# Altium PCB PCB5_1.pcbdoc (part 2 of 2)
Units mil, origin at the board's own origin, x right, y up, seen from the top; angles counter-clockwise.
Board outline 4312.83 x 4315.15 mil, 4 copper layers (Top Layer, Inner1, Inner2, Bottom Layer); 84 components, 70 nets, 244 pads, 79 vias.
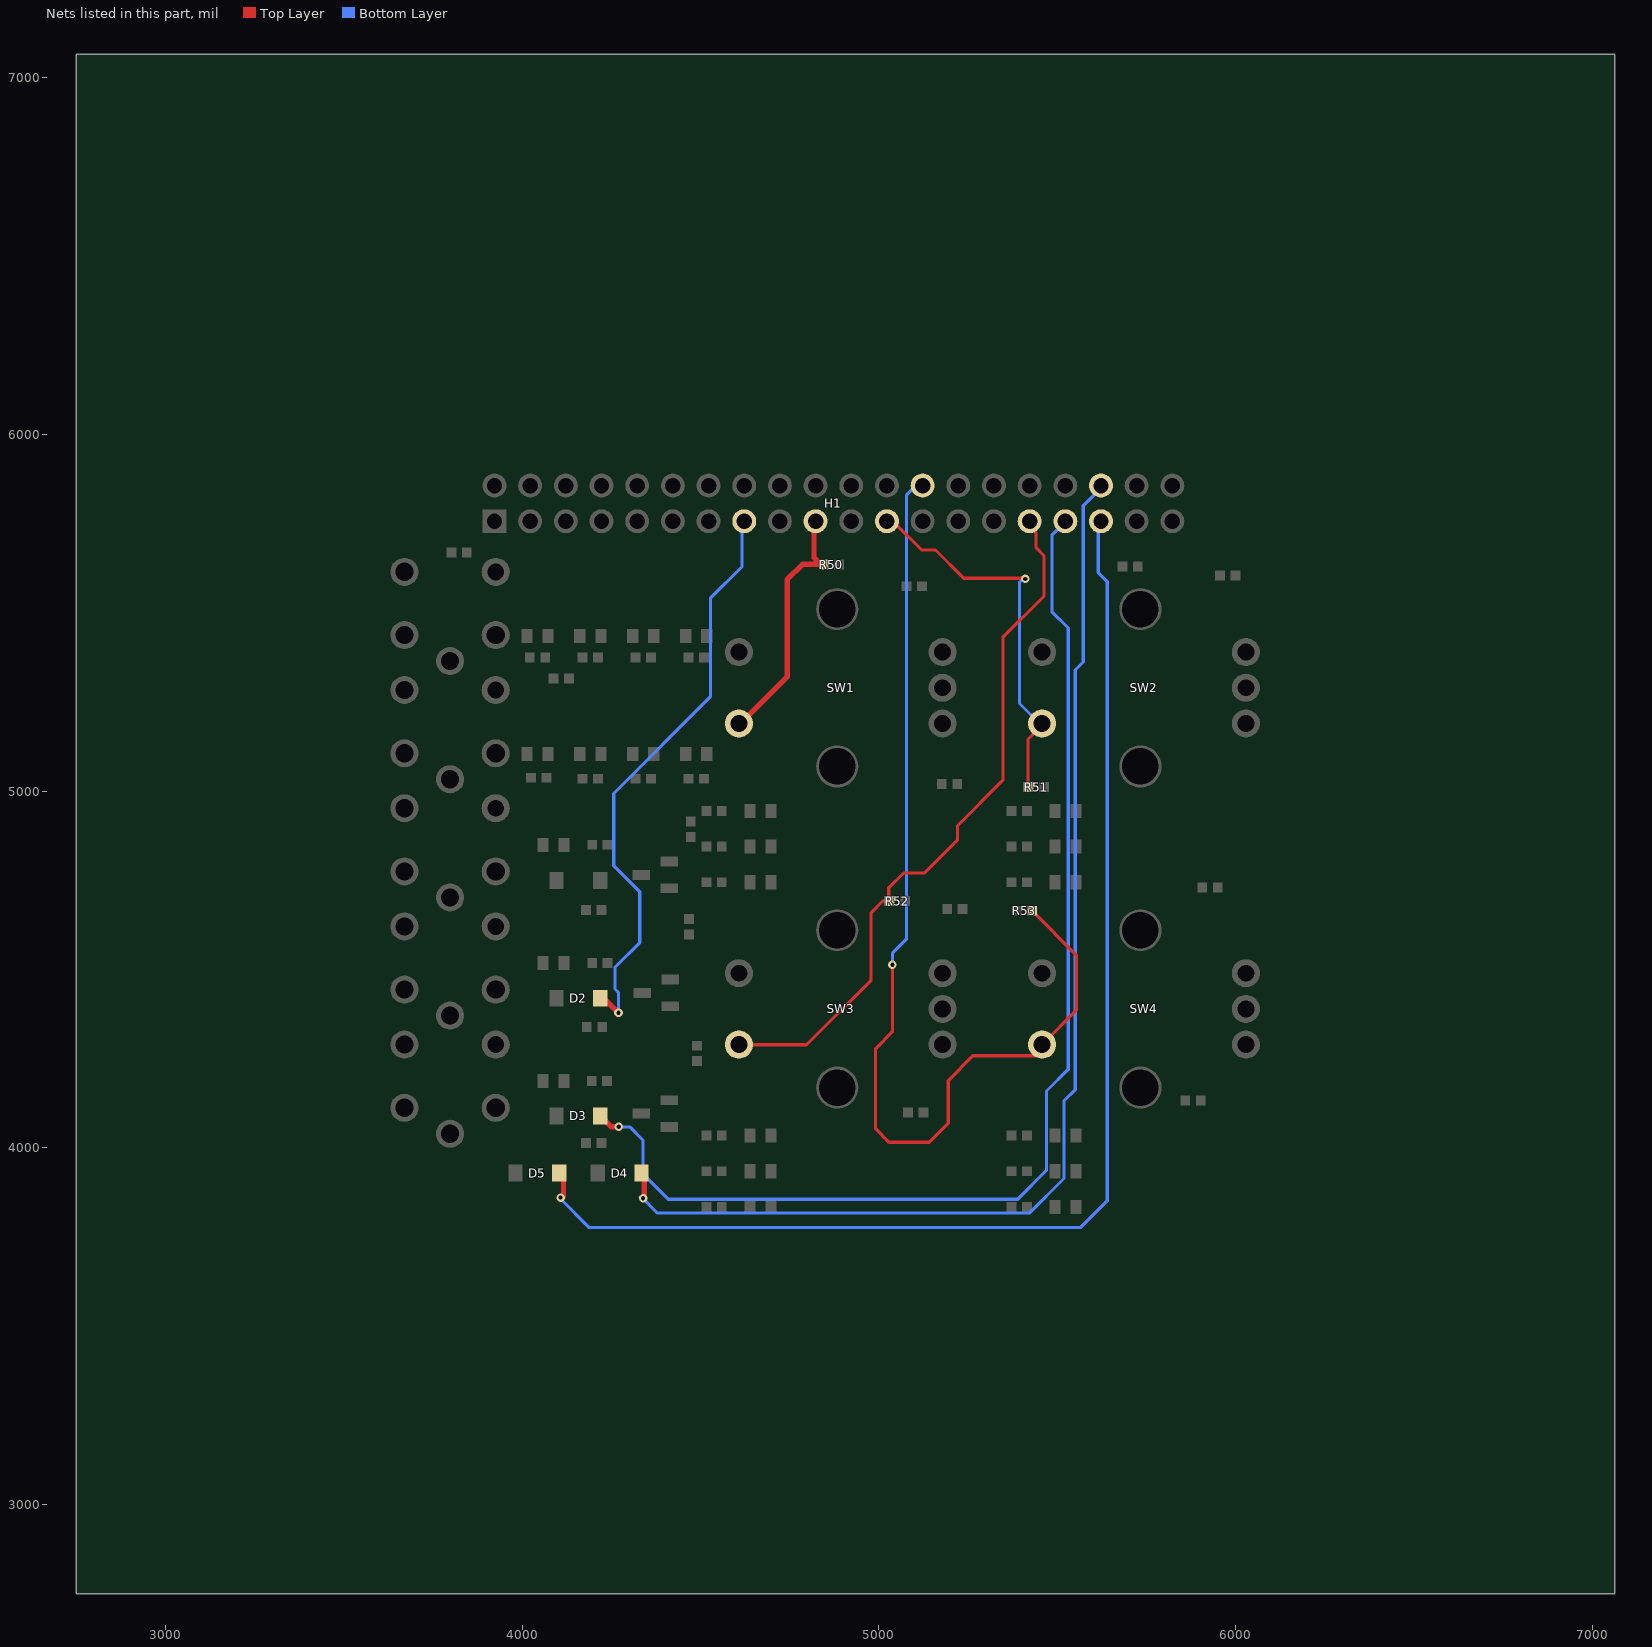
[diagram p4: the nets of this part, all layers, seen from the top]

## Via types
v1: diameter 24.02, hole 12.01, Top Layer to Bottom Layer, 69 vias
v2: diameter 30, hole 15, Top Layer to Bottom Layer, 7 vias
v3: diameter 24, hole 12, Top Layer to Bottom Layer, 2 vias
v4: diameter 32, hole 18, Top Layer to Bottom Layer, 1 vias

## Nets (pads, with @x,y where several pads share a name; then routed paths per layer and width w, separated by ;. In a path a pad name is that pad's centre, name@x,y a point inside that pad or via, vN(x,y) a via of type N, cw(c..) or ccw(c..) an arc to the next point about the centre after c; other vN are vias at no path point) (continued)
SW_BASS: H1.31 R52.1 SW3.1 | length 1952.4
  Top Layer w9: SW3.1@4617.91,4288.85 4796.83,4288.85 4978.01,4470.03 4978.01,4659.22 5010.5,4691.71 R52.1@5027.41,4691.71 ; R52.1@5028.61,4691.71 R52.1@5027.41,4691.71 ; H1.31@5434.53,5729.4 5439.76,5724.18 5439.76,5682.88 5462.65,5659.98 5462.65,5546.2 5347.42,5430.98 5347.42,5030.3 5220.5,4903.38 5220.5,4862.99 5127.44,4769.94 5068.67,4769.94 5027.41,4728.68 R52.1@5027.41,4691.71
SW_CHG_ROOM: D5.1 H1.35 | length 3568.9
  Top Layer w15: D5.1@4106.6,3924.24 4115.75,3915.09 v1@4115.75,3862.31
  Bottom Layer w9: v1@4107.8,3856.43 4187.76,3776.47 5564.57,3776.47 5639.93,3851.83 5639.93,5587.03 5614.66,5612.31 5614.66,5734.44 H1.35@5624.33,5744.11
  other v1: 4107.57,3860.48
SW_CHG_SPK: D4.1 H1.36 | length 3277.3
  Top Layer w15: D4.1@4334.61,3923.53 4342.35,3915.79 v1@4342.35,3863.01
  Bottom Layer w9: v1@4331.05,3861.57 4334.53,3861.57 4379.14,3816.97 5421.56,3816.97 5518.66,3914.06 5518.66,4131.87 5549.95,4163.16 5549.95,5339.23 5572.3,5361.59 5572.3,5799.43 5612.02,5839.15 H1.36@5612.02,5842.63
  other v1: 4338.86,3858.84
SW_EXTRA: H1.26 R53.1 SW4.1 | length 2989.2
  Top Layer w9: v1(5037.77,4513.1) 5037.77,4324.76 4990.51,4277.5 4990.51,4052.84 5027.87,4015.48 5141.08,4015.48 5193.91,4068.31 5193.91,4188.31 5263.35,4257.75 5438.83,4257.75 5461.09,4280.01 SW4.1@5461.09,4283.79 ; R53.1@5431.93,4661.05 5553.33,4539.66 5553.33,4385.55 SW4.1@5458.32,4290.55
  Bottom Layer w9: v1(5037.77,4513.1) 5037.77,4544.97 5076.79,4583.99 5076.79,5828.63 H1.26@5110.59,5862.43
SW_SINGLE_ROOM: D3.1 H1.33 | length 3292
  Top Layer w15: D3.1@4221.9,4086.45 4248.99,4059.35 v1(4270.51,4059.35)
  Bottom Layer w9: v1@4273.72,4057.96 4302.27,4057.96 4338.43,4021.8 4338.43,3926.75 4409.35,3855.83 5388.74,3855.83 5469.5,3936.59 5469.5,4159.29 5530.53,4220.33 5530.53,5456.98 5484.82,5502.69 5484.82,5717.23 H1.33@5512.18,5744.59
SW_SINGLE_SPK: D2.1 H1.15 | length 1656.8
  Top Layer w15: D2.1@4219.08,4422.82 4225.41,4422.82 v1(4269.92,4378.31)
  Bottom Layer w9: v1@4269.69,4379.42 4269.69,4435.61 4260.17,4445.13 4260.17,4506.27 4329.19,4575.29 4329.19,4717.84 4256.32,4790.71 4256.32,4993.03 4527.61,5264.31 4527.61,5540.6 4616.27,5629.27 H1.15@4616.27,5755.15
SW_TREB: H1.23 R51.1 SW2.1 | length 1071.6
  Top Layer w9: H1.23@5023.21,5744.01 5051.36,5744.01 5119.79,5675.58 5158.4,5675.58 5237.75,5596.23 v3@5410.96,5596.23 ; R51.1@5418,5012.71 5418,5145.71 SW2.1@5453.19,5180.89
  Bottom Layer w9: v3@5404.04,5595.33 5393.98,5585.27 5393.98,5245.38 SW2.1@5454.61,5184.75
  other v3: 5410.08,5594.57
SW_VOL: H1.19 R50.1 SW1.1 | length 689
  Top Layer w15: SW1.1@4608.98,5186.36 4742.57,5319.95 4742.57,5592.41 4785.6,5635.43 R50.1@4836.92,5635.43 ; H1.19@4818.05,5738.83 4818.05,5654.3 R50.1@4836.92,5635.43 ; R50.1@4839.94,5632.41 R50.1@4836.92,5635.43
pads on no net: SW1.6 SW1.7 SW2.6 SW2.7 SW3.6 SW3.7 SW4.6 SW4.7 SW5.4 SW6.4 SW7.4 SW8.4 SW9.4

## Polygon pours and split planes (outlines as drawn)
$2N557 on Bottom Layer (solid, pour order 16): 5129.22,4068.54 ccw(c5097.97,4068.18) 5066.71,4068.54 ccw(c5097.97,4068.9)
$2N1087 on Bottom Layer (solid, pour order 18): 4486.88,3980.93 ccw(c4435.15,3980.93) 4383.43,3980.93 ccw(c4435.15,3980.93)
$2N557 on Bottom Layer (solid, pour order 20): 4559.19,4097.4 ccw(c4508.6,4097.4) 4458.01,4097.4 ccw(c4508.6,4097.4)
GND on Bottom Layer (solid, remove dead copper, pour order 22): 6812.83,4906.18 ccw(c4906.65,4906.18) 3000.46,4906.18 ccw(c4906.65,4906.18)
$2N557 on Top Layer (solid, pour order 8): 4361.98,4799.29 ccw(c4313.08,4799.29) 4264.18,4799.29 ccw(c4313.08,4799.29)
$2N1087 on Top Layer (solid, pour order 10): 4366.38,4466.56 ccw(c4320.87,4466.56) 4275.36,4466.56 ccw(c4320.87,4466.56)
+3.3V on Inner2 (solid, remove dead copper): 4269,5614.61 ccw(c4181.22,5614.61) 4093.45,5614.61 ccw(c4181.22,5614.61)
$2N1617 on Top Layer (solid, pour order 12): 4361.7,4136.5 ccw(c4316.19,4136.03) 4270.69,4136.5 ccw(c4316.19,4136.97)
GND on Top Layer (solid, remove dead copper, pour order 14): 6812.37,4908.97 ccw(c4906.18,4908.97) 3000,4908.97 ccw(c4906.18,4908.97)
+5V on Inner2 (solid): 3578.15,6016.91 4068.9,6016.91 cw(c4068.9,6006.91) 4078.9,6006.91 4078.9,5001.21 cw(c4068.9,5001.21) 4068.9,4991.21 3578.15,4991.21 cw(c3578.15,5001.21) 3568.15,5001.21 3568.15,6006.91 cw(c3578.15,6006.91)
GND on Inner1 (solid, remove dead copper): 3710.9,5944 6033.73,5944 cw(c6033.73,5825.89) 6151.84,5825.89 6151.84,3857.39 cw(c6033.73,3857.39) 6033.73,3739.28 3710.9,3739.28 cw(c3710.9,3857.39) 3592.79,3857.39 3592.79,5825.89 cw(c3710.9,5825.89)
+5V on Top Layer (solid, remove dead copper, pour order 0): 5542.79,5033.03 5641.57,5033.03 cw(c5641.57,5023.03) 5651.57,5023.03 5651.57,4669.27 cw(c5641.57,4669.27) 5641.57,4659.27 5542.79,4659.27 cw(c5542.79,4669.27) 5532.79,4669.27 5532.79,5023.03 cw(c5542.79,5023.03)
+5V on Top Layer (solid, remove dead copper, pour order 2): 4692.79,5029.27 4761.81,5029.27 cw(c4761.81,5019.27) 4771.81,5019.27 4771.81,4698.36 cw(c4761.81,4698.36) 4761.81,4688.36 4692.79,4688.36 cw(c4692.79,4698.36) 4682.79,4698.36 4682.79,5019.27 cw(c4692.79,5019.27)
+5V on Inner2 (solid): 3838.9,5258.45 5620.13,5258.45 cw(c5620.13,5248.45) 5630.13,5248.45 5630.13,4989.81 cw(c5620.13,4989.81) 5620.13,4979.81 3838.9,4979.81 cw(c3838.9,4989.81) 3828.9,4989.81 3828.9,5248.45 cw(c3838.9,5248.45)
+5V on Inner2 (solid): 4646.95,5057.39 4769.98,5057.39 cw(c4769.98,5047.39) 4779.98,5047.39 4779.98,3951.12 cw(c4769.98,3951.12) 4769.98,3941.12 4646.95,3941.12 cw(c4646.95,3951.12) 4636.95,3951.12 4636.95,5047.39 cw(c4646.95,5047.39)
+5V on Top Layer (solid, remove dead copper, pour order 4): 4690.3,4203.83 4771.25,4203.83 cw(c4771.25,4193.83) 4781.25,4193.83 4781.25,3801.93 cw(c4771.25,3801.93) 4771.25,3791.93 4690.3,3791.93 cw(c4690.3,3801.93) 4680.3,3801.93 4680.3,4193.83 cw(c4690.3,4193.83)
+5V on Inner2 (solid): 5463.44,5064.52 5623.41,5064.52 cw(c5623.41,5054.52) 5633.41,5054.52 5633.41,3944 cw(c5623.41,3944) 5623.41,3934 5463.44,3934 cw(c5463.44,3944) 5453.44,3944 5453.44,5054.52 cw(c5463.44,5054.52)
+5V on Top Layer (solid, remove dead copper, pour order 6): 5543.92,4148.17 5617.79,4148.17 cw(c5617.79,4138.17) 5627.79,4138.17 5627.79,3812.23 cw(c5617.79,3812.23) 5617.79,3802.23 5543.92,3802.23 cw(c5543.92,3812.23) 5533.92,3812.23 5533.92,4138.17 cw(c5543.92,4138.17)
+5V on Inner2 (solid): 3998.06,5202.59 4152.95,5202.59 cw(c4152.95,5192.59) 4162.95,5192.59 4162.95,4053.57 cw(c4152.95,4053.57) 4152.95,4043.57 3998.06,4043.57 cw(c3998.06,4053.57) 3988.06,4053.57 3988.06,5192.59 cw(c3998.06,5192.59)
+3.3V on Inner2 (solid): 4110.95,6017.23 6203.95,6017.23 cw(c6203.95,6007.23) 6213.95,6007.23 6213.95,5307.86 cw(c6203.95,5307.86) 6203.95,5297.86 4110.95,5297.86 cw(c4110.95,5307.86) 4100.95,5307.86 4100.95,6007.23 cw(c4110.95,6007.23)
+3.3V on Inner2 (solid): 5659.48,5375.97 6201.57,5375.97 cw(c6201.57,5365.97) 6211.57,5365.97 6211.57,3687.81 cw(c6201.57,3687.81) 6201.57,3677.81 5659.48,3677.81 cw(c5659.48,3687.81) 5649.48,3687.81 5649.48,5365.97 cw(c5659.48,5365.97)
+3.3V on Inner2 (solid): 4840.88,4948.46 5403.56,4948.46 cw(c5403.56,4938.46) 5413.56,4938.46 5413.56,3590.44 cw(c5403.56,3590.44) 5403.56,3580.44 4840.88,3580.44 cw(c4840.88,3590.44) 4830.88,3590.44 4830.88,4938.46 cw(c4840.88,4938.46)
+3.3V on Inner2 (solid): 4208.76,4941.34 4588.52,4941.34 cw(c4588.52,4931.34) 4598.52,4931.34 4598.52,3512.06 cw(c4588.52,3512.06) 4588.52,3502.06 4208.76,3502.06 cw(c4208.76,3512.06) 4198.76,3512.06 4198.76,4931.34 cw(c4208.76,4931.34)
+3.3V on Inner2 (solid): 3474.83,4943.71 3940.95,4943.71 cw(c3940.95,4933.71) 3950.95,4933.71 3950.95,3533.44 cw(c3940.95,3533.44) 3940.95,3523.44 3474.83,3523.44 cw(c3474.83,3533.44) 3464.83,3533.44 3464.83,4933.71 cw(c3474.83,4933.71)
+3.3V on Inner2 (solid): 3289.58,3911.36 5781.19,3911.36 cw(c5781.19,3901.36) 5791.19,3901.36 5791.19,3497.81 cw(c5781.19,3497.81) 5781.19,3487.81 3289.58,3487.81 cw(c3289.58,3497.81) 3279.58,3497.81 3279.58,3901.36 cw(c3289.58,3901.36)
+3.3V on Inner2 (solid): 3970.82,4005.97 4197.43,4005.97 cw(c4197.43,3995.97) 4207.43,3995.97 4207.43,3406.77 cw(c4197.43,3406.77) 4197.43,3396.77 3970.82,3396.77 cw(c3970.82,3406.77) 3960.82,3406.77 3960.82,3995.97 cw(c3970.82,3995.97)
+3.3V on Inner2 (solid, remove dead copper): 3877.89,5796.37 3943.98,5796.37 cw(c3943.98,5781.37) 3958.98,5781.37 3958.98,5724.09 cw(c3943.98,5724.09) 3943.98,5709.09 3877.89,5709.09 cw(c3877.89,5724.09) 3862.89,5724.09 3862.89,5781.37 cw(c3877.89,5781.37)

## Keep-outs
Board Outline Layer:
  circle w1: c3730.58,3877.07 r53.15
  circle w10: c3730.58,3877.07 r53.15
  circle w1: c3730.58,5806.2 r53.15
  circle w10: c3730.58,5806.2 r53.15
  circle w1: c6014.05,3877.07 r53.15
  circle w10: c6014.05,3877.07 r53.15
  circle w1: c6014.05,5806.2 r53.15
  circle w10: c6014.05,5806.2 r53.15
  lines w10: 3592.79,3857.39 ccw(c3710.9,3857.39) 3710.9,3739.28 6033.73,3739.28 ccw(c6033.73,3857.39) 6151.84,3857.39 6151.84,5825.89 ccw(c6033.73,5825.89) 6033.73,5944 3710.9,5944 ccw(c3710.9,5825.89) 3592.79,5825.89 3592.79,3857.39

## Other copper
Top Layer:
  drawing of 211 lines, arcs and shapes, not listed
Inner2:
  region net +3.3V: 3975.4,5714.84 3941.26,5696.66 ccw(c3876.18,5631.57) 3888.85,5722.74 3955.78,5773.71 ccw(c4053.89,5773.71)
  region net +3.3V: 4709.74,5710.18 4678.12,5730.89 4680.31,5733.2 4682.42,5735.69 4684.36,5738.33 4686.06,5741.11 4687.45,5744 4688.45,5746.98 4688.99,5750.03 4688.99,5753.14 4729.52,5723.52 4726.63,5722.68 4723.89,5721.51 4721.29,5720.05 4718.81,5718.36 4716.43,5716.47 4714.14,5714.45
Bottom Layer:
  region net SW_SINGLE_SPK: 4620.77,5706.48 4611.77,5715.54 4611.62,5717.17 4611.18,5718.76 4610.49,5720.32 4609.58,5721.85 4607.23,5724.83 4604.41,5727.72 4598.38,5733.36 4595.72,5736.15 4594.59,5737.55 4593.63,5738.96 4643.01,5729.9 4638.86,5726.96 4634.84,5724.54 4631.09,5722.38 4627.72,5720.21 4626.23,5719.05 4624.88,5717.8 4623.69,5716.42 4622.69,5714.87 4621.87,5713.14 4621.27,5711.18 4620.9,5708.97
  region net SW_ALL_ROOM: 4601.15,5819.99 4588.27,5819.84 4589.94,5821.69 4591.24,5823.52 4592.2,5825.32 4592.85,5827.12 4593.23,5828.93 4593.37,5830.75 4593.31,5832.59 4593.07,5834.47 4592.23,5838.39 4591.1,5842.58 4589.97,5847.13 4589.1,5852.13 4630.51,5823.76 4628.84,5823.43 4627.04,5823.23 4623.19,5823.13 4614.96,5823.4 4610.92,5823.35 4607.16,5822.9 4605.44,5822.47 4603.85,5821.85 4602.41,5821.03
  region net ALL_ROOM_LED: 4692.95,5820.85 4686.87,5827.51 4687.8,5828.68 4688.53,5830.11 4689.07,5831.76 4689.45,5833.6 4689.81,5837.71 4689.77,5842.19 4689.16,5851.2 4688.92,5855.22 4688.94,5858.57 4724.14,5822.79 4721.36,5822.75 4718.81,5822.91 4716.46,5823.24 4714.28,5823.67 4706.85,5825.61 4705.19,5825.92 4703.55,5826.06 4701.92,5825.99 4700.27,5825.66 4698.57,5825.03 4696.8,5824.05 4694.94,5822.67
  region net SINGLE_SPK_LED: 4907.31,5819.74 4889.62,5814.78 4891.21,5816.55 4892.46,5818.35 4893.42,5820.18 4894.11,5822.05 4894.54,5823.95 4894.75,5825.89 4894.76,5827.86 4894.6,5829.88 4893.85,5834.03 4892.7,5838.35 4889.99,5847.54 4934.96,5825.22 4933.18,5824.61 4931.37,5824.18 4927.69,5823.76 4923.98,5823.69 4920.3,5823.73 4916.73,5823.61 4915,5823.41 4913.33,5823.07 4911.71,5822.57 4910.17,5821.87 4908.69,5820.93
  region net SINGLE_ROOM_LED: 4991.66,5821.05 4986.7,5828.82 4987.64,5830 4988.38,5831.43 4988.94,5833.07 4989.33,5834.89 4989.7,5838.95 4989.67,5843.36 4989.11,5852.25 4988.92,5856.25 4989.03,5859.61 5023.09,5822.75 5020.35,5822.79 5017.81,5823.02 5013.28,5823.85 5009.3,5824.9 5005.71,5825.8 5004,5826.1 5002.33,5826.23 5000.66,5826.14 4998.98,5825.81 4997.26,5825.18 4995.48,5824.2 4993.62,5822.84
  region net SW_EXTRA: 5079.97,5825.44 5085.84,5844.04 5087.15,5845.52 5088.16,5847.02 5088.91,5848.56 5089.45,5850.12 5089.8,5851.71 5090.01,5853.32 5090.14,5856.63 5090.14,5860.04 5090.28,5863.54 5090.5,5865.33 5090.87,5867.13 5091.43,5868.96 5092.21,5870.81 5111.59,5824.51 5102.8,5827.67 5098.64,5829.01 5094.63,5829.92 5092.68,5830.16 5090.76,5830.22 5088.88,5830.08 5087.03,5829.71 5085.22,5829.08 5083.44,5828.18 5081.69,5826.98
  region net CLK_VOL: 5228.63,5712.03 5219.63,5709.32 5219.5,5711.95 5219.15,5714.22 5218.58,5716.17 5217.81,5717.84 5216.85,5719.28 5215.72,5720.53 5214.43,5721.64 5213.01,5722.66 5209.8,5724.58 5206.23,5726.67 5202.4,5729.27 5200.43,5730.87 5198.45,5732.75 5248.57,5735.46 5246.29,5732.97 5243.35,5730.27 5236.73,5724.4 5233.62,5721.32 5231.04,5718.2 5230.04,5716.64 5229.28,5715.09 5228.79,5713.55
  region net CLK_BASS: 5350.31,5712.87 5330.62,5719.84 5328.95,5721.36 5327.36,5722.52 5325.83,5723.37 5324.34,5723.95 5322.9,5724.32 5321.47,5724.52 5318.61,5724.6 5315.67,5724.56 5312.52,5724.78 5310.83,5725.1 5309.04,5725.63 5307.15,5726.41 5305.14,5727.48 5352.96,5742.75 5349.22,5734.54 5347.64,5730.63 5346.5,5726.85 5346.16,5725 5346.01,5723.18 5346.06,5721.39 5346.35,5719.63 5346.89,5717.9 5347.72,5716.2 5348.85,5714.52
  region net SW_SINGLE_ROOM: 5494.58,5720.63 5487.11,5725.89 5488.91,5727.86 5490.27,5729.72 5491.25,5731.49 5491.88,5733.2 5492.21,5734.88 5492.29,5736.54 5492.16,5738.2 5491.87,5739.9 5490.95,5743.47 5489.91,5747.43 5489.1,5751.97 5488.89,5754.51 5488.87,5757.26 5525.45,5722.89 5522.09,5722.81 5518.09,5723.01 5509.16,5723.58 5504.73,5723.61 5500.66,5723.24 5498.83,5722.86 5497.19,5722.31 5495.76,5721.57
  region net SW_CHG_ROOM: 5619.16,5705.49 5610.16,5716.97 5610.02,5718.66 5609.59,5720.28 5608.93,5721.85 5608.06,5723.37 5605.82,5726.28 5603.12,5729.09 5597.36,5734.61 5594.81,5737.44 5593.73,5738.9 5592.82,5740.4 5641.69,5728.92 5637.49,5726.18 5633.42,5723.82 5629.61,5721.63 5626.2,5719.38 5624.69,5718.17 5623.32,5716.86 5622.12,5715.43 5621.1,5713.85 5620.28,5712.1 5619.67,5710.13 5619.29,5707.94
  region net SW_CHG_SPK: 5599.36,5820.12 5587.92,5821.42 5589.63,5823.3 5590.94,5825.13 5591.9,5826.93 5592.55,5828.71 5592.91,5830.48 5593.04,5832.26 5592.95,5834.06 5592.7,5835.9 5591.83,5839.73 5590.72,5843.87 5589.67,5848.42 5589.25,5850.89 5588.96,5853.51 5629.16,5823.45 5625.73,5823.05 5621.82,5823.04 5613.39,5823.4 5609.24,5823.37 5605.39,5822.95 5603.64,5822.52 5602.03,5821.93 5600.6,5821.14
  region net DT_TREB: 5752.59,5708.41 5728.31,5719.96 5726.63,5721.5 5725.04,5722.67 5723.53,5723.54 5722.09,5724.15 5720.68,5724.55 5719.31,5724.77 5716.58,5724.93 5713.77,5724.99 5710.77,5725.34 5709.15,5725.74 5707.44,5726.36 5705.61,5727.24 5703.65,5728.43 5752.21,5741.15 5750.32,5737.01 5748.78,5732.69 5747.7,5728.31 5747.36,5726.12 5747.17,5723.94 5747.14,5721.79 5747.29,5719.67 5747.63,5717.61 5748.17,5715.6 5748.92,5713.67 5749.9,5711.82 5751.12,5710.06
  region net CLK_EXTRA: 5693.62,5820.76 5686.97,5826.83 5688.79,5828.82 5690.16,5830.69 5691.14,5832.46 5691.77,5834.15 5692.1,5835.81 5692.17,5837.44 5692.03,5839.07 5691.73,5840.74 5689.78,5848.17 5689.35,5850.34 5689.03,5852.69 5688.86,5855.25 5688.9,5858.03 5724.68,5822.82 5721.34,5822.8 5717.32,5823.05 5708.3,5823.66 5703.82,5823.7 5699.71,5823.34 5697.87,5822.96 5696.22,5822.41 5694.8,5821.69
  region net CLK_TREB: 5858.38,5833.06 5856.94,5821.78 5855.06,5823.48 5853.22,5824.8 5851.42,5825.76 5849.65,5826.41 5847.88,5826.77 5846.1,5826.89 5844.31,5826.81 5842.48,5826.55 5838.65,5825.68 5834.52,5824.57 5829.97,5823.53 5827.49,5823.12 5824.87,5822.84 5855.1,5862.91 5855.49,5859.48 5855.49,5855.57 5855.12,5847.11 5855.15,5842.95 5855.57,5839.09 5855.99,5837.34 5856.58,5835.73 5857.37,5834.3
  region net SW_TREB: 5415.51,5217.48 5416.43,5229.29 5418.71,5227.22 5420.92,5225.64 5423.07,5224.5 5425.18,5223.76 5427.27,5223.37 5429.36,5223.28 5431.47,5223.44 5433.63,5223.81 5438.13,5224.98 5443.03,5226.42 5448.49,5227.73 5451.48,5228.23 5454.66,5228.55 5418.7,5181.71 5418.42,5183.7 5418.3,5185.85 5418.39,5190.54 5419.1,5200.66 5419.2,5205.63 5419.08,5207.99 5418.81,5210.24 5418.34,5212.34 5417.66,5214.27 5416.72,5215.99
  region net CLK_BASS: 5239.47,4321.91 5219.61,4289.32 5217.87,4287.43 5216.51,4285.64 5215.47,4283.94 5214.7,4282.3 5214.15,4280.72 5213.76,4279.19 5213.27,4276.17 5212.8,4273.13 5212.44,4271.57 5211.92,4269.95 5211.2,4268.27 5210.22,4266.51 5208.93,4264.65 5207.27,4262.68 5200.99,4321.4 5203.15,4320.01 5205.44,4318.77 5207.84,4317.7 5210.34,4316.81 5212.9,4316.09 5215.51,4315.56 5218.15,4315.23 5220.79,4315.09 5223.41,4315.16 5225.99,4315.44 5228.51,4315.94 5230.95,4316.66 5233.29,4317.61 5235.5,4318.8 5237.57,4320.23
  region net $2N6348: 3720.44,5294.35 3726.19,5279.35 3723.38,5279.22 3720.89,5278.83 3718.68,5278.21 3716.71,5277.36 3714.95,5276.31 3713.35,5275.07 3711.89,5273.67 3710.52,5272.11 3707.92,5268.6 3705.27,5264.68 3702.27,5260.49 3700.55,5258.34 3698.63,5256.17 3692.89,5314.94 3695.76,5312.58 3698.96,5309.56 3706.04,5302.72 3709.74,5299.51 3713.43,5296.85 3715.25,5295.81 3717.03,5295.03 3718.76,5294.53
  region net $2N6348: 3869.39,5279.35 3875.13,5294.35 3876.81,5294.53 3878.55,5295.03 3880.33,5295.81 3882.15,5296.85 3885.84,5299.51 3889.54,5302.72 3896.62,5309.56 3899.82,5312.58 3902.69,5314.94 3896.95,5256.17 3895.03,5258.34 3893.31,5260.49 3890.31,5264.68 3887.66,5268.6 3885.06,5272.11 3883.69,5273.67 3882.23,5275.07 3880.63,5276.31 3878.87,5277.36 3876.9,5278.21 3874.68,5278.83 3872.2,5279.22
  region net $2N6353: 3729.21,4950.76 3716.44,4935.76 3714.65,4935.61 3712.86,4935.16 3711.07,4934.46 3709.28,4933.53 3705.73,4931.14 3702.21,4928.27 3695.37,4922.14 3692.07,4919.43 3688.88,4917.32 3701.65,4974.97 3704.75,4970.46 3707.57,4966.08 3710.3,4961.99 3713.12,4958.33 3714.63,4956.7 3716.23,4955.23 3717.95,4953.94 3719.82,4952.84 3721.86,4951.96 3724.08,4951.31 3726.53,4950.9
  region net $2N6353: 3879.14,4935.76 3866.37,4950.76 3869.05,4950.9 3871.5,4951.31 3873.72,4951.96 3875.76,4952.84 3877.62,4953.94 3879.35,4955.23 3880.95,4956.7 3882.46,4958.33 3885.28,4961.99 3888.01,4966.08 3890.83,4970.46 3893.93,4974.97 3906.7,4917.32 3903.51,4919.43 3900.21,4922.14 3893.36,4928.27 3889.85,4931.14 3886.29,4933.53 3884.51,4934.46 3882.72,4935.16 3880.93,4935.61
  region net $2N6363: 3719.91,4632.51 3726.63,4617.51 3723.85,4617.37 3721.36,4616.98 3719.15,4616.35 3717.17,4615.5 3715.39,4614.44 3713.78,4613.2 3712.29,4611.78 3710.9,4610.21 3708.27,4606.67 3705.61,4602.73 3702.64,4598.51 3699.07,4594.15 3692.35,4652.82 3695.26,4650.49 3698.48,4647.51 3705.53,4640.76 3709.21,4637.6 3712.88,4634.97 3714.69,4633.95 3716.47,4633.17 3718.22,4632.68
  region net $2N6363: 3868.95,4617.51 3875.67,4632.51 3877.36,4632.68 3879.11,4633.17 3880.89,4633.95 3882.7,4634.97 3886.37,4637.6 3890.05,4640.76 3897.1,4647.51 3900.32,4650.49 3903.23,4652.82 3896.51,4594.15 3892.94,4598.51 3889.97,4602.73 3887.3,4606.67 3884.67,4610.21 3883.29,4611.78 3881.8,4613.2 3880.19,4614.44 3878.41,4615.5 3876.43,4616.35 3874.21,4616.98 3871.73,4617.37
  region net $2N6358: 3724.56,4295.25 3722.28,4280.25 3719.31,4280.13 3716.75,4279.77 3714.55,4279.19 3712.65,4278.4 3711,4277.43 3709.56,4276.28 3708.26,4274.98 3707.06,4273.53 3704.74,4270.28 3702.19,4266.65 3700.7,4264.73 3698.99,4262.77 3697.01,4260.77 3694.72,4258.76 3697,4317.77 3699.08,4315.66 3700.91,4313.57 3704,4309.5 3706.61,4305.7 3709.09,4302.29 3710.39,4300.77 3711.79,4299.41 3713.32,4298.21 3715.03,4297.19 3716.97,4296.36 3719.18,4295.76 3721.69,4295.38
  region net $2N6358: 3873.3,4280.25 3871.02,4295.25 3873.88,4295.38 3876.4,4295.76 3878.61,4296.36 3880.55,4297.19 3882.26,4298.21 3883.79,4299.41 3885.19,4300.77 3886.49,4302.29 3888.97,4305.7 3891.58,4309.5 3894.67,4313.57 3896.5,4315.66 3898.57,4317.77 3900.86,4258.76 3898.57,4260.77 3896.59,4262.77 3894.88,4264.73 3893.39,4266.65 3890.83,4270.28 3888.52,4273.53 3887.32,4274.98 3886.02,4276.28 3884.57,4277.43 3882.93,4278.4 3881.03,4279.19 3878.83,4279.77 3876.27,4280.13
  region net DT_TREB: 6052.89,5596.01 6052.89,5605.01 6054.13,5605.11 6055.29,5605.4 6056.38,5605.84 6057.42,5606.42 6059.39,5607.86 6061.3,5609.52 6061.3,5591.5 6059.39,5593.16 6057.42,5594.6 6056.38,5595.18 6055.29,5595.62 6054.13,5595.91
  region net CLK_TREB: 5892.68,5701.12 5896.82,5709.71 5897.75,5708.94 5898.82,5708.33 5899.99,5707.86 5901.24,5707.54 5903.82,5707.25 5906.35,5707.36 5896.04,5692.59 5895.52,5695.02 5894.98,5697.21 5894.14,5699.22 5893.51,5700.18
  region net CLK_EXTRA: 5992.24,4102.44 6001.24,4102.19 6001.34,4100.95 6001.63,4099.8 6002.06,4098.71 6002.63,4097.68 6004.06,4095.71 6005.69,4093.78 5987.68,4094.03 5989.36,4095.93 5990.82,4097.91 5991.4,4098.95 5991.85,4100.05 5992.14,4101.21
  region net SW_EXTRA: 5033.27,4529.44 5042.27,4529.44 5042.37,4528.21 5042.66,4527.05 5043.1,4525.96 5043.68,4524.92 5045.12,4522.95 5046.78,4521.04 5028.77,4521.04 5030.42,4522.95 5031.86,4524.92 5032.44,4525.96 5032.88,4527.05 5033.17,4528.21
  region net SW_CHG_ROOM: 4121.69,3848.9 4112.46,3845.4 4111.52,3846.23 4110.58,3846.87 4108.63,3847.75 4104.14,3848.97 4119.42,3858.51 4119.23,3856 4119.51,3853.37 4119.84,3852.1 4120.31,3850.91 4120.92,3849.83
  region net SW_ALL_ROOM: 4254.58,4717.5 4257.47,4727.35 4258.39,4726.59 4259.48,4725.97 4260.69,4725.5 4261.99,4725.16 4264.65,4724.89 4267.14,4725.13 4258.37,4709.4 4256.97,4713.77 4256.06,4715.65
  region net SW_SINGLE_SPK: 4265.19,4394.49 4274.19,4394.83 4274.3,4393.6 4274.59,4392.44 4275.04,4391.34 4275.63,4390.29 4277.09,4388.32 4278.78,4386.43 4260.77,4386.08 4262.39,4388.01 4263.81,4389.98 4264.81,4392.1 4265.09,4393.25
  region net SW_SINGLE_ROOM: 4287.85,4062.46 4285.76,4053.46 4284.51,4053.37 4283.38,4053.11 4281.32,4052.21 4279.38,4050.94 4277.35,4049.48 4279.45,4067.37 4281.23,4065.57 4283.24,4063.99 4284.32,4063.36 4285.45,4062.88 4286.63,4062.57
  region net SW_CHG_SPK: 4353.38,3849.1 4345.82,3843.92 4344.88,3844.74 4343.89,3845.36 4341.77,3846.17 4339.47,3846.62 4336.99,3846.97 4350.86,3858.47 4350.88,3855.93 4351.2,3853.42 4351.52,3852.22 4351.98,3851.08 4352.59,3850.04
  region net SINGLE_SPK_LED: 4512.7,4672.28 4519.06,4665.91 4518.26,4664.97 4517.64,4663.95 4517.18,4662.86 4516.86,4661.72 4516.48,4659.31 4516.3,4656.78 4503.57,4669.52 4506.09,4669.7 4508.5,4670.08 4509.64,4670.4 4510.73,4670.86 4511.75,4671.48
  region net ALL_ROOM_LED: 4549.76,4908.7 4558.76,4908.7 4558.86,4907.47 4559.14,4906.31 4559.59,4905.22 4560.16,4904.18 4561.61,4902.21 4563.26,4900.3 4545.25,4900.3 4546.9,4902.21 4548.35,4904.18 4548.92,4905.22 4549.37,4906.31 4549.65,4907.47
  region net SINGLE_ROOM_LED: 4534.76,4345.88 4541.12,4339.51 4540.32,4338.57 4539.7,4337.55 4539.25,4336.46 4538.92,4335.32 4538.54,4332.9 4538.36,4330.38 4525.63,4343.12 4528.15,4343.3 4530.56,4343.67 4531.7,4344 4532.79,4344.46 4533.81,4345.07
  region net $2N557: 5307.9,4901.52 5307.9,4916.52 5310.27,4916.45 5312.41,4916.45 5313.42,4916.58 5314.4,4916.86 5315.36,4917.33 5316.3,4918.03 5316.3,4900.02 5315.36,4900.72 5314.4,4901.19 5313.42,4901.47 5312.41,4901.6 5310.27,4901.6
  region net $2N1087: 5441.85,4779.85 5423.85,4775.62 5424,4777.1 5424.36,4778.41 5425.21,4780.6 5425.44,4781.54 5425.37,4782.4 5424.89,4783.23 5423.85,4784.03 5440.3,4788.25 5439.96,4787.32 5439.95,4786.32 5440.17,4785.28 5440.55,4784.19 5441.41,4781.99 5441.73,4780.9
  region net $2N1087: 5338.25,3921.61 5338.25,3903.61 5336.81,3903.72 5335.61,3904 5333.65,3904.65 5332.78,3904.82 5331.9,3904.77 5330.94,3904.4 5329.85,3903.6 5329.85,3921.61 5330.94,3920.82 5331.9,3920.44 5332.78,3920.39 5333.65,3920.57 5335.61,3921.22 5336.81,3921.49
  region net $2N557: 4336.18,4809.76 4315.78,4787.72 4311.61,4791.62 4308.53,4794.05 4305.41,4796.43 4301.1,4800.19 4322.89,4823.62 4326.56,4820.03 4329.6,4816.77 4332.61,4813.47
  region net $2N1617: 5265.62,4184.88 5270.24,4164.05 5269.02,4162.99 5267.85,4162.23 5265.63,4161.18 5264.58,4160.67 5263.56,4160.01 5262.57,4159.11 5261.59,4157.85 5256.62,4179.02 5258.09,4178.41 5259.34,4178.39 5260.42,4178.85 5261.41,4179.7 5263.33,4182.13 5264.4,4183.52
  region net SW_TREB: 5397.16,5582.08 5394.96,5592.62 5396.47,5594.38 5397.51,5596.1 5399.4,5600.06 5405.97,5583.3 5403.71,5583.83 5401.31,5583.86 5400.13,5583.66 5399.03,5583.3 5398.02,5582.78
  region net $2N557: 4532.15,4105.06 cw(c4543.82,4169.01) 4478.81,4169.01 4448.81,4169.01 4449.1,4089.91 4504.42,4073.45 cw(c4532.15,3836) 4532.15,4075.06
  region net $2N557: 5095.6,4111.38 5110.6,4115.15 ccw(c5262.1,4115.15) 5113.6,4085.15 5093.15,4081.38 ccw(c4910.44,4111.38)
  region net $2N1087: 5361.87,3921.61 5361.87,3903.61 ccw(c5361.87,3617.59) 5332.61,3902.11 5332.61,3923.11 ccw(c5361.87,4207.63)

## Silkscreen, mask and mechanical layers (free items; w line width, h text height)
Top Silkscreen Layer:
  text "SPEAKER SELECT" at 3997.79,5544.27 h80
  text "C" at 4027.79,5464.27 h70
  text "L" at 4176.09,5464.27 h70
  text "R" at 4320.44,5464.27 h70
  text "S" at 4470.44,5464.27 h70
  text "ROOM SELECT" at 3997.79,5211.77 h80
  text "LIV" at 3990.44,5131.77 h68
  text "KIT" at 4132.29,5131.77 h68
  text "BED" at 4272.29,5131.77 h68
  text "OFF" at 4422.29,5131.77 h68
  text "ROOM1-LIVING" at 4757.79,4909.27 h65
  text "ROOM2-KITCHEN" at 5599.29,4909.27 h65
  text "ALL ROOMS" at 3997.79,4901.77 h80
  text "VOLUME" at 4757.79,4809.27 h65
  text "BASS" at 5599.29,4809.27 h65
  text "Z1-CENTER" at 4757.79,4709.27 h65
  text "Z2-LEFT" at 5599.29,4709.27 h65
  text "SINGLE RM" at 3997.79,4559.27 h80
  text "SINGLE SPK" at 3997.79,4231.77 h80
  text "ROOM3-BEDROOM" at 4757.79,3996.78 h65
  text "ROOM4-OFFICE" at 5599.29,3996.78 h65
  text "TREBLE" at 4757.79,3896.78 h65
  text "CUSTOM" at 5599.29,3896.78 h65
  text "Z3-RIGHT" at 4757.79,3801.78 h65
  text "Z4-ANY" at 5599.29,3801.78 h65
  text "SONOS_HAT-ZAMAN-2025" at 3821.23,3746.85 h65
Bottom Silkscreen Layer:
  region: 5638.6,4057.38 5835.45,4057.38 5835.45,3860.53 5638.6,3860.53
Top Solder Mask Layer:
  circle w64.96: c3730.58,3877.07 r85.63
  circle w64.96: c3730.58,5806.2 r85.63
  circle w64.96: c6014.05,3877.07 r85.63
  circle w64.96: c6014.05,5806.2 r85.63
Bottom Solder Mask Layer:
  circle w64.96: c3730.58,3877.07 r85.63
  circle w64.96: c3730.58,5806.2 r85.63
  circle w64.96: c6014.05,3877.07 r85.63
  circle w64.96: c6014.05,5806.2 r85.63
  circle w64.96: c6014.05,3877.07 r85.63
  circle w64.96: c3730.58,3877.07 r85.63
  circle w64.96: c3730.58,5806.2 r85.63
  circle w64.96: c6014.05,5806.2 r85.63
Mechanical Layer:
  circle w1: c3730.58,3877.07 r53.15
  circle w1: c3730.58,5806.2 r53.15
  circle w1: c6014.05,3877.07 r53.15
  circle w1: c6014.05,5806.2 r53.15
